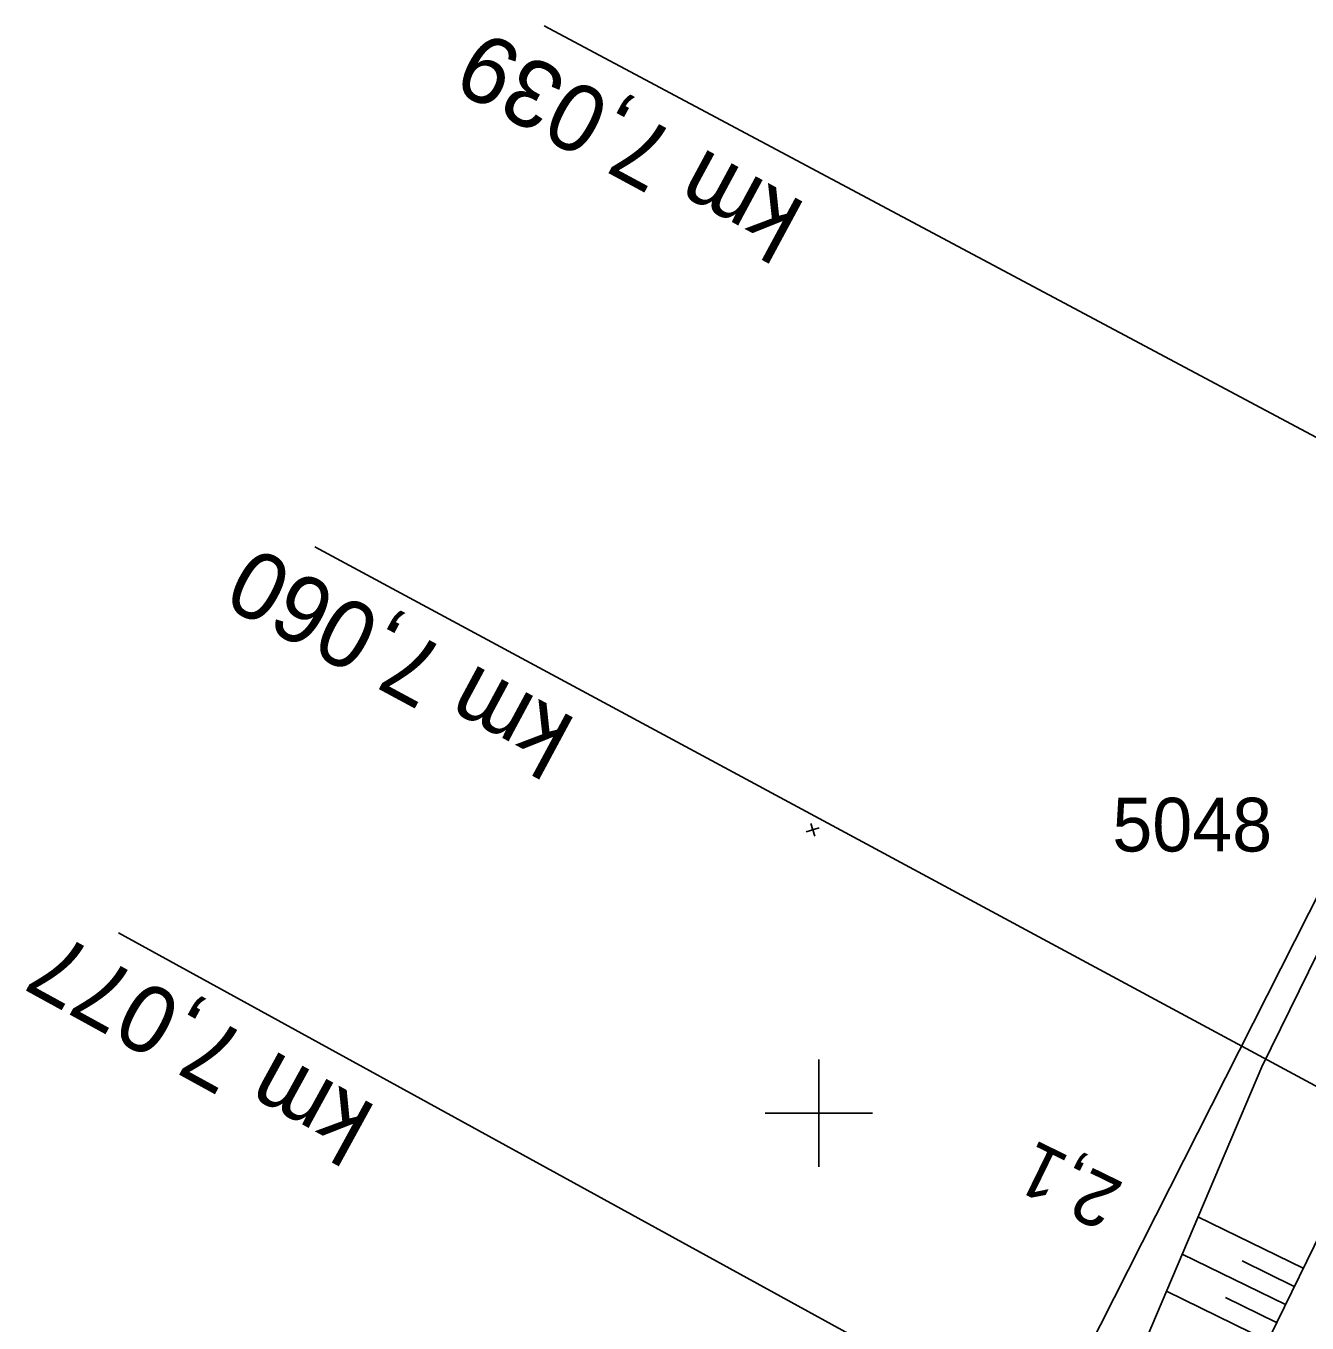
# Model space of a CAD drawing. Extents: x -795094 to -794639, y -1135368 to -1134681.
# Drawn here: x -794929.52 to -794881.82, y -1135007.81 to -1134959.53 of the extents above; entities that cross this region are included whole.
import ezdxf

# ---------------------------------------------------------------- set-up
doc = ezdxf.new("R2010")
doc.units = 0
for name, color, linetype in [('0381KM005-009P - Vrstva 3', 7, 'Continuous'), ('0381KM005-009P - Vrstva 48', 7, 'Continuous'), ('0381KM005-009P - Vrstva 49', 7, 'Continuous'), ('0381KM005-009P - Vrstva 6', 7, 'Continuous'), ('0381KM005-009P - Vrstva 8', 7, 'Continuous'), ('krizky_1000 - Vrstva 1', 7, 'Continuous'), ('szdc - hran DP', 7, 'Continuous'), ('szdc - szdc_cislo', 7, 'Continuous')]:
    doc.layers.add(name, color=color, linetype=linetype)

msp = doc.modelspace()

# ---------------------------------------------------------------- linework, layer by layer
at = {"layer": '0381KM005-009P - Vrstva 3'}
msp.add_line((-794882.938, -1135016.954), (-794926.069, -1134993.289), dxfattribs=at)
at = {"layer": '0381KM005-009P - Vrstva 48'}
for p, q in [((-794881.969, -1135005.772), (-794885.885, -1135003.859)), ((-794882.628, -1135007.12), (-794886.473, -1135005.241)), ((-794882.298, -1135006.446), (-794884.239, -1135005.498)), ((-794883.286, -1135008.468), (-794887.061, -1135006.624)), ((-794882.957, -1135007.794), (-794884.862, -1135006.863))]:
    msp.add_line(p, q, dxfattribs=at)
at = {"layer": '0381KM005-009P - Vrstva 49'}
for p, q in [((-794868.24, -1134967.149), (-794883.505, -1134998.267)), ((-794899.985, -1134989.378), (-794900.465, -1134989.522)), ((-794900.297, -1134989.21), (-794900.153, -1134989.69)), ((-794883.505, -1134998.267), (-794891.468, -1135016.979)), ((-794879, -1134999.695), (-794890.343, -1135022.912))]:
    msp.add_line(p, q, dxfattribs=at)
at = {"layer": '0381KM005-009P - Vrstva 6'}
msp.add_line((-794877.804, -1135000.976), (-794918.759, -1134978.921), dxfattribs=at)
at = {"layer": '0381KM005-009P - Vrstva 8'}
msp.add_line((-794867.871, -1134982.096), (-794910.227, -1134959.525), dxfattribs=at)
at = {"layer": 'krizky_1000 - Vrstva 1'}
for points in [[(-794900, -1134998), (-794900, -1135002)], [(-794902, -1135000), (-794898, -1135000)]]:
    msp.add_lwpolyline(points, dxfattribs=at)
at = {"layer": 'szdc - hran DP'}
msp.add_line((-794899.86, -1135028.32), (-794880.53, -1134990.11), dxfattribs=at)

# ---------------------------------------------------------------- texts
at = {"layer": '0381KM005-009P - Vrstva 3'}
msp.add_text('km 7,077', height=2.5, rotation=151.2467, dxfattribs=at).set_placement((-794916.408, -1134999.776))
at = {"layer": '0381KM005-009P - Vrstva 48'}
msp.add_text('2,1', height=2, rotation=153.9615, dxfattribs=at).set_placement((-794888.582, -1135002.628))
at = {"layer": '0381KM005-009P - Vrstva 6'}
msp.add_text('km 7,060', height=2.5, rotation=151.6961, dxfattribs=at).set_placement((-794908.965, -1134985.366))
at = {"layer": '0381KM005-009P - Vrstva 8'}
msp.add_text('km 7,039', height=2.5, rotation=151.6652, dxfattribs=at).set_placement((-794900.417, -1134966.163))
at = {"layer": 'szdc - szdc_cislo'}
msp.add_text('5048', height=2, dxfattribs=at).set_placement((-794889.072, -1134990.256))

doc.saveas('drawing.dxf')
